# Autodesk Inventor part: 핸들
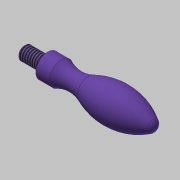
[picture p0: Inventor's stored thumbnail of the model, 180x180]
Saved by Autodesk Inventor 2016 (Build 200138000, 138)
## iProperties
Created: 2019-10
Part Number: 핸들
Material: 스테인리스강
Document SubType Name: Modeling
Designer: mduedu
Density: 1 g/cm^3
Appearance: 보라색
Author: mduedu
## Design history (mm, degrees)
sketch "스케치1"
  geometry: L1 (0, 0)-(0, 2); L2 (0, 2)-(7, 2); L3 (7, 2)-(7, 3.5); L4 (7, 3.5)-(11, 3.5); L5 (0, 0)-(39, 0); A1 r 9.5 centre (15.243, 12) between (11, 3.5) and (19.07, 3.305); A2 r 20 centre (27.128, -15) between (38.049, 1.754) and (19.07, 3.305); A3 r 2.094 centre (36.906, 0) between (39, 0) and (38.049, 1.754)
  constraints: 10 end point, 6 point on circle, 3 centre point, 3 parallel, 2 tangent, 1 perpendicular, 1 point on line, 1 vertical
  dimensions: "d0" = 39 distance of L1.start L5.end; "d1" = 4 diameter of L2 L5; "d2" = 7 diameter of L4 L5; "d3" = 7 distance of L1.end L2.end; "d4" = 4 distance of L3.end L4.end; "d5" = 5 dimension on A1 L5; "d6" = 9.5 radius of A1; "d7" = 10 dimension on A2 L5; "d8" = 20 radius of A2
revolve "회전1" sketch "스케치1" stored, may be unused: angle "d9" = 90 deg
feature "스레드1" dims "d10" = 6, "d11" = 0
chamfer "모따기1" distance "d12" = 0.5; stored, may be unused: second distance "d13" = 2, angle "d14" = 45 deg
node "솔리드1"
